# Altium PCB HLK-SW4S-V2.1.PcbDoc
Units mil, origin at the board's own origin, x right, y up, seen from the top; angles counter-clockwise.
Board outline 2716.54 x 2598.43 mil, 2 copper layers (Top Layer, Bottom Layer); 72 components, 59 nets, 226 pads, 137 vias.
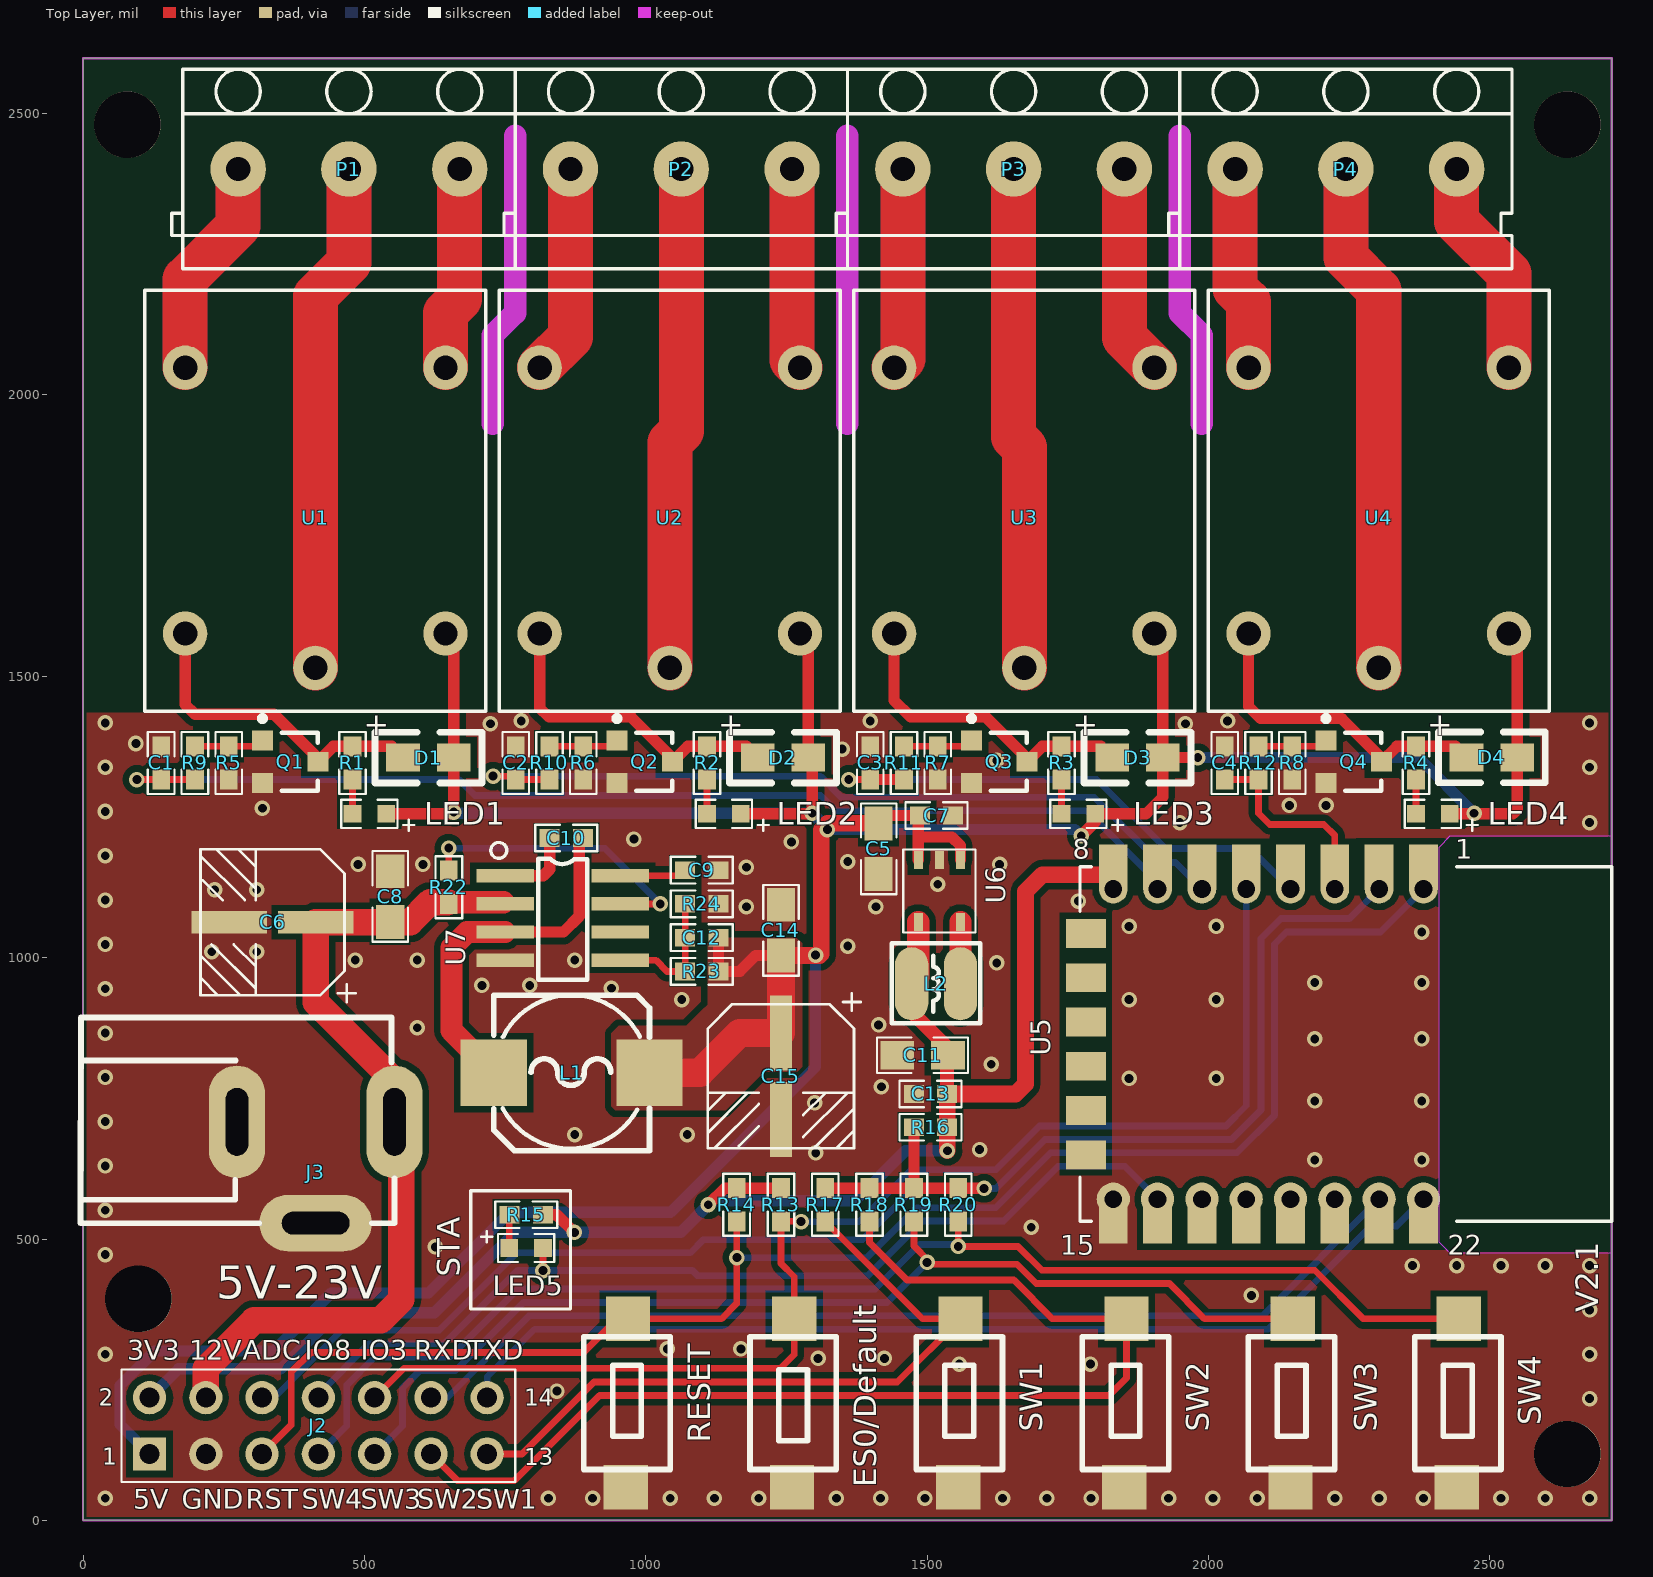
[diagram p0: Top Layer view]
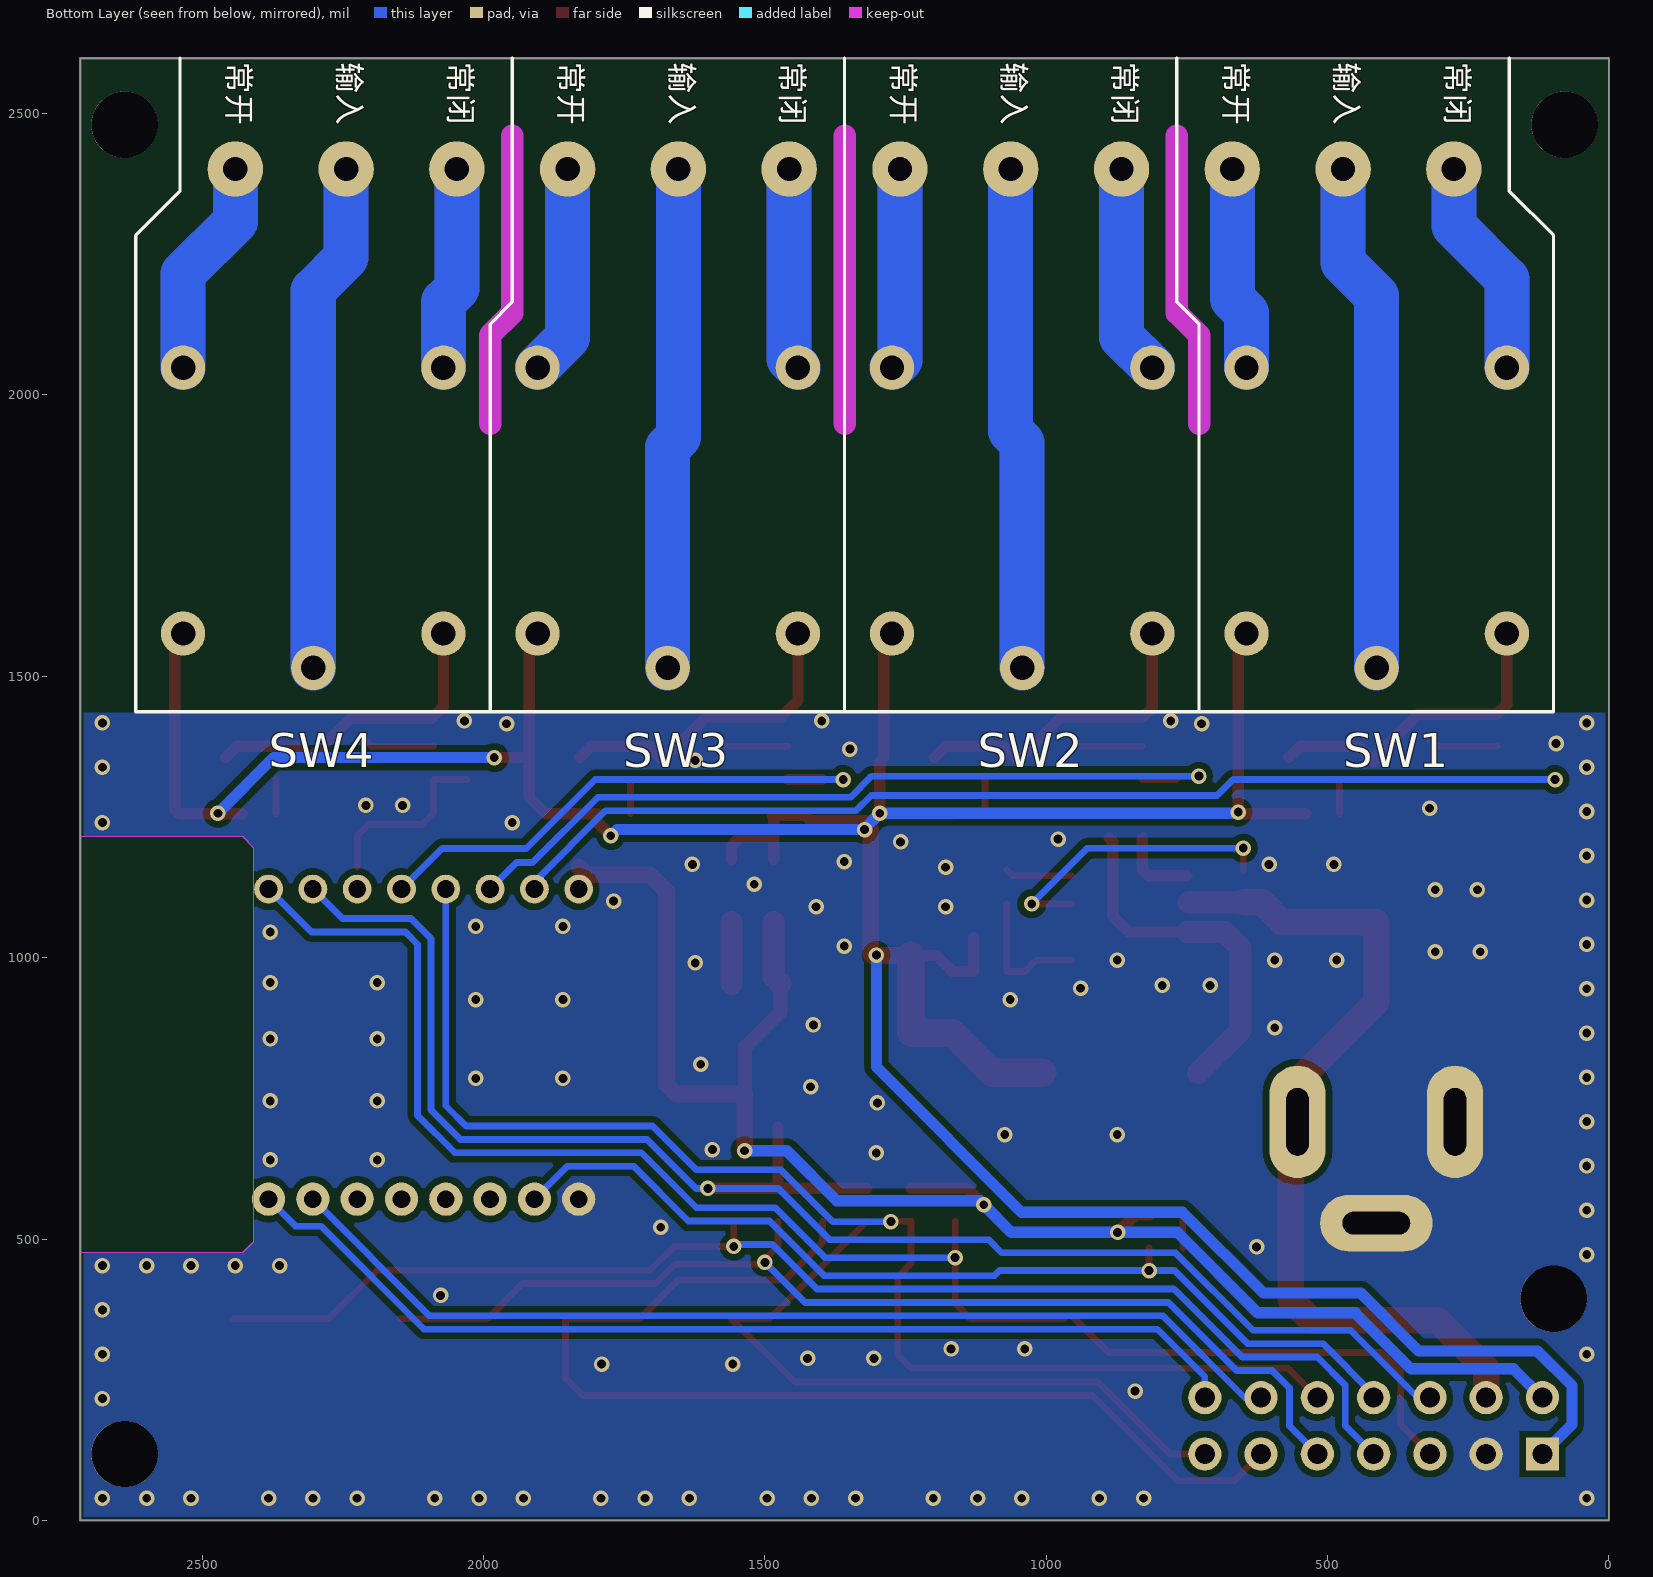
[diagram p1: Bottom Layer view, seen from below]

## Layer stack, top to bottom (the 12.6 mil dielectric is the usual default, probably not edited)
Top Layer: signal copper 1.4
Dielectric: dielectric 12.6, FR-4, Dk 4.8
Bottom Layer: signal copper 1.4

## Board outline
0,0 2716.54,0 2716.54,2598.43 0,2598.43

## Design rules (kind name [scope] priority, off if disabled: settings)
Clearance Clearance_1 [OnLayer('Keep-Out Layer')] p1: gap=3.94
Clearance [All] p2: gap=11.81
FabricationTestPointUsage TestPointUsage [All] p1: valid=0 allowmultiple=FALSE
FabricationTestpoint Testpoint [All] p1: side=3 testpointundercomponent=TRUE minsize=40 maxsize=100 preferedsize=60 minholesize=0 maxholesize=40 preferedholesize=32 testpointgrid=1 allowsidetop=TRUE allowsidebottom=TRUE usegrid=TRUE gridtolerance=0.01
PlaneConnect [All] p1: planeconnectstyle=Direct reliefexpansion=20 reliefentries=4 reliefconductorwidth=10 reliefairgap=10
PolygonConnect [All] p1: connectstyle=Direct reliefconductorwidth=10 reliefentries=4 polygonreliefangle="90 Angle" airgapwidth=10
RoutingVias [All] p1: holewidth=15.75 width=27.56 viastyle="Through Hole" minholewidth=15.75 minwidth=27.56 maxholewidth=15.75 maxwidth=27.56
SilkToSolderMaskClearance SilkscreenOverComponentPads [IsPad] p1: minsilkscreentomaskgap=10 clearancetoexposedcopper=TRUE
SolderMaskExpansion [All] p1: expansion=4
Width [All] p1: maxlimit=236.22 minlimit=10 preferedwidth=10
24 further rules are at their usual default settings.

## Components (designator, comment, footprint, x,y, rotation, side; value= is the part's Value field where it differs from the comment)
C1 "0.1uF" 0603L 138.74,1346.14 r270 top
C2 "0.1uF" 0603L 768.74,1346.14 r270 top
C3 "0.1uF" 0603L 1398.74,1346.14 r270 top
C4 "0.1uF" 0603L 2028.74,1346.14 r270 top
C5 "10uF/16V" 0805S 1413.74,1238.67 r270 top
C6 "220uF/35V" CAP_SMT_6.3 425.2,1062.99 r270 top
C7 "0.1uF" 0603L 1516.74,1252.67 r180 top
C8 "22uF" 0805S 545.74,1063.67 r90 top
C9 "0.1UF" 0603L 1099.53,1155.67 r180 top
C10 "0.1uF" 0603L 858.74,1212.67 r180 top
C11 "10uF/16V" 0805S 1536.85,826.77 r180 top
C12 "100pf" 0603L 1099.53,1035.67 r180 top
C13 "0.1uF" 0603L 1505.91,757.87 r0 top
C14 "0.1UF" 0805S 1240.16,1093.94 r270 top
C15 "220uF" CAP_SMT_6.3 1240.16,877.95 r0 top
D1 "1N4148" LED1 568.94,1355.43 r0 top
D2 "1N4148" LED1 1198.94,1355.43 r0 top
D3 "1N4148" LED1 1828.94,1355.43 r0 top
D4 "1N4148" LED1 2458.74,1355.67 r0 top
ES0/Default "SW-PB" KEY 1185.04,326.77 r270 top
J2 "HEADER 7X2" HDR2X7 118.11,118.11 r0 top
J3 "PWR2.5" POWER_STK1 413.39,728.35 r0 top
L1 "10uH" L7x7 730,795.67 r0 top
L2 "2.7uH" L322520 1559.06,953.78 r180 top
LED1 "LED" 0603LED 508.74,1255.67 r180 top
LED2 "LED" 0603LED 1138.74,1255.67 r180 top
LED3 "LED" 0603LED 1768.74,1255.67 r180 top
LED4 "LED" 0603LED 2398.74,1255.67 r180 top
LED5 "LED" 0603LED 787.4,484.25 r0 top
P1 "Header 3" 5MMX3 669.29,2401.57 r180 top
P2 "Header 3" 5MMX3 1259.84,2401.57 r180 top
P3 "Header 3" 5MMX3 1850.4,2401.57 r180 top
P4 "Header 3" 5MMX3 2440.95,2401.57 r180 top
Q1 "SS8050" SOT-23 367.95,1348.27 r270 top
Q2 "SS8050" SOT-23 997.95,1348.27 r270 top
Q3 "SS8050" SOT-23 1627.95,1348.27 r270 top
Q4 "SS8050" SOT-23 2257.95,1348.27 r270 top
R1 "1K" 0603L 478.74,1346.14 r270 top
R2 "1K" 0603L 1108.74,1346.14 r270 top
R3 "1K" 0603L 1738.74,1346.14 r270 top
R4 "1K" 0603L 2368.74,1346.14 r270 top
R5 "4.7K" 0603L 258.74,1346.14 r90 top
R6 "4.7K" 0603L 888.74,1346.14 r90 top
R7 "4.7K" 0603L 1518.74,1346.14 r90 top
R8 "4.7K" 0603L 2148.74,1346.14 r90 top
R9 "1K" 0603L 198.74,1346.14 r270 top
R10 "1K" 0603L 828.74,1346.14 r90 top
R11 "1K" 0603L 1458.74,1346.14 r270 top
R12 "1K" 0603L 2088.74,1346.14 r270 top
R13 "NC" 0603L 1240.16,561.02 r270 top
R14 "1K" 0603L 1161.42,561.02 r270 top
R15 "1K" 0603L 787.4,543.31 r0 top
R16 "10K" 0603L 1505.91,698.82 r0 top
R17 "521" 0603L 1318.9,561.02 r90 top
R18 "1.19K" 0603L 1397.64,561.02 r90 top
R19 "0" 0603L 1476.38,561.02 r90 top
R20 "3.04K" 0603L 1555.12,561.02 r90 top
R22 "10K" 0603L 650,1125.2 r90 top
R23 "47k" 0603L 1099.53,975.67 r0 top
R24 "10K" 0603L 1099.53,1095.67 r0 top
RESET "SW-PB" KEY 1043.31,90.55 r90 top
SW1 "SW-PB" KEY 1633.86,90.55 r90 top
SW2 "SW-PB" KEY 1929.13,90.55 r90 top
SW3 "SW-PB" KEY 2224.41,90.55 r90 top
SW4 "SW-PB" KEY 2519.68,90.55 r90 top
U1 "SRD-05VDC-SL-C" SRD-05VDC-SL-C 715.83,1438.27 r90 top
U2 "SRD-05VDC-SL-C" SRD-05VDC-SL-C 1345.75,1438.27 r90 top
U3 "SRD-05VDC-SL-C" SRD-05VDC-SL-C 1975.67,1438.27 r90 top
U4 "SRD-05VDC-SL-C" SRD-05VDC-SL-C 2605.59,1438.27 r90 top
U5 "WIFI MODULE" MOD1 1771.65,1161.42 r270 top
U6 "RT8009" SOT-25 1559.06,1173.78 r270 top
U7 "FR9886" SOP8 750.36,1140.67 r0 top

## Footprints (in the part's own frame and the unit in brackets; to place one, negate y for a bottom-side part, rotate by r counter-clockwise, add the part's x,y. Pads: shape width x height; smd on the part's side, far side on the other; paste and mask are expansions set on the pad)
5MMX3 [mm]
  round 2.5 hole 1.1: 1(0,0) 2(5,0) 3(10,0)
  silkscreen extent -2.5,-4.5 13,4.5
0603L [mm]
  rect 0.9x0.8 smd: 1(-0.75,0) 2(0.75,0)
  silkscreen extent -1.4,-0.6 1.4,0.6
0603LED [mm]
  rect 0.8x0.8 smd: 1(-0.762,0) 2(0.762,0)
  silkscreen extent -2.03,-0.64 1.27,0.76
0805S [mil]
  rect 60x50 smd: 1(0,0) 2(90,0)
  silkscreen extent -35,-31 126,31
CAP_SMT_6.3 [mm]
  rect 1x3.4 smd: 1(0,-0.3) 2(0,-4.2)
  silkscreen extent -3.3,-5.5 3.6,1.5
HDR2X7 [mm] "Connector; Header; 7x2 Position"
  rect 1.5x1.5 hole 0.9: 1(0,0)
  round 1.5 hole 0.9: 2(0,2.54) 3(2.54,0) 4(2.54,2.54) 5(5.08,0) 6(5.08,2.54) 7(7.62,0) 8(7.62,2.54) 9(10.16,0) 10(10.16,2.54) 11(12.7,0) 12(12.7,2.54) 13(15.24,0) 14(15.24,2.54)
  silkscreen extent -1.27,-1.27 16.51,3.81
KEY [mm]
  rect 2x2 smd: 1(-0.8,2) 2(6.8,1.9)
  silkscreen extent 0,0 6,3.9
L7x7 [mm]
  rect 3x3 smd: 1(0,0) 2(7.025,0)
  silkscreen extent 0,-3.53 7.03,3.5
L322520 [mm]
  oval 1.5x3.3 smd: 1(0,0) 2(2.2,0)
  silkscreen extent -0.9,-1.83 3.09,1.79
LED1 [mil]
  rect 60x50 smd: 1(-0.2,0.24) 2(89.8,0.24)
  silkscreen extent -50,-45 140,45
MOD1 [mm]
  rect 2x1.3 smd: 1(0,15.5) 2(0,13.5) 3(0,11.5) 4(0,9.5) 5(0,7.5) 6(0,5.5) 7(0,3.5) 8(0,1.5) 15(16,1.5) 16(16,3.5) 17(16,5.5) 18(16,7.5) 19(16,9.5) 20(16,11.5) 21(16,13.5) 22(16,15.5)
  round 1.3 hole 0.8: 1(1,15.5) 2(1,13.5) 3(1,11.5) 4(1,9.5) 5(1,7.5) 6(1,5.5) 7(1,3.5) 8(1,1.5)
  rect 1.3x1.8 smd: 9(3,0.262) 10(5,0.262) 11(7,0.262) 12(9,0.262) 13(11,0.262) 14(13,0.262)
  round 1.5 hole 0.8: 15(15,1.5) 16(15,3.5) 17(15,5.5) 18(15,7.5) 19(15,9.5) 20(15,11.5) 21(15,13.5) 22(15,15.5)
  silkscreen extent 0,0 16,24
POWER_STK1 [mil]
  oval 100x200 hole 40 slot 120 at 90 deg: 1(-140,-20) 2(140,-20)
  oval 200x100 hole 40 slot 120 at 0 deg: 3(0,-200)
  silkscreen extent -418,-200 140,165
SOP8 [mm] "Small Outline; 8 Leads; Body Width 4.3 mm; Pitch 1.27 mm"
  rect 2.6x0.6 smd: 1(-0.009,0.127) 2(-0.009,-1.143) 3(-0.009,-2.413) 4(-0.009,-3.683) 5(5.191,-3.683) 6(5.191,-2.413) 7(5.191,-1.143) 8(5.191,0.127)
  silkscreen extent 1.49,-4.57 3.69,0.89
SOT-23 [mm]
  rect 0.9x0.95 smd: 1(-0.95,-1.25) 2(0.95,-1.25) 3(0,1.25)
  silkscreen extent -2.07,-1.37 1.3,1.25
SOT-25 [mm]
  rect 0.8x0.4 smd: 1(0,0) 2(0,-0.95) 3(0,-1.9) 4(2.8,-1.9) 5(2.8,0)
  silkscreen extent -0.48,-2.58 3.28,0.68
SRD-05VDC-SL-C [mm]
  round 2 hole 1.1: 1(15.5,1.825) 2(15.5,13.575) 3(3.5,13.575) 4(1.95,7.7) 5(3.5,1.825)
  silkscreen extent 0,0 19,15.4

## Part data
C1 C2 C3 C4 C7 C8 C9 C10 C12 C13: library part Cap, "Capacitor"
C5 C6 C11 C15: library part "Cap Pol3", "Polarized Capacitor (Surface Mount)"
C14 R1 R2 R3 R4 R5 R6 R7 R8 R9 R10 R11 R12 R13 R14 R15 R16 R17 R18 R19 R20: library part Res2, "Resistor"
D1 D2 D3 D4: library part Diode, "Default Diode"
ES0/Default RESET SW1 SW2 SW3 SW4: "Switch"
J3: "Low Voltage Power Supply Connector"
L1 L2: library part INDUCTOR1
LED1 LED2 LED3 LED4 LED5: library part LED0, "Typical INFRARED GaAs LED"
P1 P2 P3 P4: "Header, 3-Pin"
Q1 Q2 Q3 Q4: library part 2N3904, "PNP General Purpose Amplifier"
R22 R23 R24: library part "0603_10 K_1%_1/10W", "RES, SO, 0603, 10K, 1%, 1/10W"
U1 U2 U3 U4: library part SRD
U5: library part MOD1

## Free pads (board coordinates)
  round 118.11 hole 118.11: 0(98.43,393.7) 0(2637.8,118.11) 0(2637.8,2480.32) 1(78.74,2480.32)

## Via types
v1: diameter 27.56, hole 15.75, Top Layer to Bottom Layer, tented both sides, 137 vias

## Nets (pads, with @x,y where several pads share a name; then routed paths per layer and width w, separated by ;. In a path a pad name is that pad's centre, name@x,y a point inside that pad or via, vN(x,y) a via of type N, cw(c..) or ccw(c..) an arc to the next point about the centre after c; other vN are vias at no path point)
5V: C5.1 C7.2 C12.1 C14.2 C15.1 D1.2 D2.2 D3.2 D4.2 J2.1 L1.2 LED1.1 LED2.1 LED3.1 LED4.1 R23.2 U1.5 U2.5 U3.5 U4.5 U6.1 U6.3 | length 6580.8
  Top Layer w19.68: U1.5 658.74,1561.3 D1.2
  Top Layer w20: LED1.1 655.74,1255.67 v1(658.74,1258.67) D1.2 ; C12.1 R23.2 1166.74,975.67 1195.01,1003.94 C14.2 ; LED2.1 1294.74,1255.67 v1(1295.74,1256.67) 1295.74,1348.67 D2.2 1288.74,1561.22 U2.5 ; C5.1 1427.74,1252.67 C7.2 ; U6.3 C7.2@1484.25,1241.18 ; 1486.74,1214.67 1543.74,1214.67 1559.06,1199.35 U6.1 ; v1(1773.74,1216.67) 1798.74,1241.67 LED3.1 1888.74,1255.67 1918.74,1285.67 D3.2 ; U3.5 1918.74,1561.14 D3.2 ; v1(1980.74,1355.67) D3.2 ; LED4.1 2540.74,1255.67 2548.54,1263.47 D4.2 2548.54,1561.27 U4.5
  Top Layer w29.53: C14.2 1309.01,1003.94 1311.74,1006.67 v1@1311.74,1227.67 ; v1@1322.74,1238.67 C5.1
  Top Layer w50: L1.2 1096,795.67 1166.47,866.14 C15.1 C14.2
  Bottom Layer w20: J2.1 65.74,170.48 65.74,239.67 127.33,301.26 338.26,301.26 441,404 614,404 757.59,547.59 1043.59,547.59 1301.74,805.74 v1(1301.74,1004.67) ; v1(658.74,1258.67) 660.74,1256.67 v1(1295.74,1256.67) v1@1324.74,1227.67 ; v1(1322.74,1227.67) v1@1324.74,1227.67 ; v1(1773.74,1216.67) 1762.74,1227.67 v1@1324.74,1227.67 ; v1(1980.74,1355.67) 2372.74,1355.67 v1(2471.74,1256.67)
ADC: J2.6 R16.1 R17.2 R18.2 R19.2 R20.2 U5.2 | length 2928.3
  Top Layer w20: R17.2 R18.2 R19.2 ; R16.1 R19.2 ; v1(1601,590) 1600.45,590.55 R20.2 R19.2
  Bottom Layer w12: J2.6 339.43,218.11 459.32,338 632.32,338 769.91,475.59 1079,475.59 1102.41,499 1385,499 1476,590 v1(1601,590) 1622.33,590 1709.52,677.19 2040.86,677.19 2093.19,729.52 2093.19,1033.86 2128.81,1069.48 2250.58,1069.48 U5.2@2303.15,1122.05
GND: C1.1 C2.1 C3.1 C4.1 C5.2 C6.2 C7.1 C8.2 C9.1 C11.2 C13.1 C14.1 C15.2 ES0/Default.2 J2.3 J3.1 J3.3 pad.0@98.43,393.7 pad.0@2637.8,118.11 Q1.2 Q2.2 Q3.2 Q4.2 R5.1 R6.1 R7.1 R8.1 R24.2 RESET.1 SW1.1 SW2.1 SW3.1 SW4.1 U5.15 U6.2 U7.4
  other v1: 39.37,39.37 826.77,39.37 905.51,39.37 1043.31,39.37 1122.05,39.37 1200.79,39.37 1338.58,39.37 1417.32,39.37 1496.06,39.37 1633.86,39.37 1712.6,39.37 1791.34,39.37 1929.13,39.37 2007.87,39.37 2086.61,39.37 2224.41,39.37 2303.15,39.37 2381.89,39.37 2519.69,39.37 2598.43,39.37 2677.17,39.37 2677.17,216.54 842,230 1557,278 1790,278 1306,288 1424,288 39.37,295.28 2677.17,295.28 1038,305 1169,305 2677.17,374.02 2076,400 2362.2,452.76 2440.94,452.76 2519.69,452.76 2598.43,452.76 2677.17,452.76 39.37,472.44 626,486 1685,521 39.37,551.18 39.37,629.92 2188.74,640.67 2378.74,640.67 1302,653 1593,659 873.74,685.67 1073.74,685.67 39.37,708.66 1300,742 2188.74,745.67 2378.74,745.67 1418.74,770.67 1858.74,785.67 2013.74,785.67 39.37,787.4 1613.74,810.67 2188.74,855.67 2378.74,855.67 39.37,866.14 593.74,875.67 1413.74,880.67 1063.74,925.67 1858.74,925.67 2013.74,925.67 39.37,944.88 938.74,945.67 708.74,950.67 793.74,950.67 2188.74,955.67 2378.74,955.67 1623.74,990.67 483.74,995.67 593.74,995.67 873.74,995.67 228.74,1010.67 308.74,1010.67 1358.74,1020.67 39.37,1023.62 2378.74,1045.67 1858.74,1055.67 2013.74,1055.67 1178.74,1090.67 1408.74,1090.67 1768.74,1100.67 39.37,1102.36 233.74,1120.67 308.74,1120.67 1518.74,1130.67 1178.74,1160.67 488.74,1165.67 603.74,1165.67 1628.74,1165.67 1358.74,1170.67 39.37,1181.1 1258.74,1205.67 978.74,1210.67 1948.82,1240.16 2677.17,1240.16 39.37,1259.84 318.74,1265.67 2143.74,1270.67 2208.74,1270.67 39.37,1338.58 2677.17,1338.58 1623.74,1350.67 1348.74,1370.67 93.74,1380.67 723.74,1415.67 1958.74,1415.67 39.37,1417.32 2677.17,1417.32 778.74,1420.67 1398.74,1420.67 2033.74,1420.67
IO0: U5.12
IO1: C4.2 R12.2 U5.3 | length 327.6
  Top Layer w12: C4.2 R12.2 2088.74,1256.67 2108.74,1236.67 2204.74,1236.67 2224.41,1217 U5.3@2224.41,1161.42
IO2: C3.2 R11.2 U5.4 | length 963.6
  Top Layer w12: v1(1360.74,1316.67) 1398.69,1316.67 C3.2
  Top Layer w19.68: C3.2 R11.2
  Bottom Layer w12: v1(1360.74,1316.67) 1801.33,1316.67 1924,1194 2073.72,1194 U5.4@2145.67,1122.05
IO3: ES0/Default.1 J2.10 R13.2 U5.5 | length 2321.4
  Top Layer w12: J2.10 570.67,270.67 1239.74,270.67 1263.78,294.71 ES0/Default.1 1263.78,433.07 1240.16,456.69 R13.2 1275.5,531.5 v1(1276,531)
  Bottom Layer w12: v1(1276,531) 1379.43,531 1471.43,623 1621.65,623 1699.65,701 2031,701 2066.93,736.93 U5.5@2066.93,1122.05
IO4: U5.13
IO5: U5.14
IO7: U5.17
IO8: J2.8 LED5.2 U5.16 | length 1737.5
  Top Layer w12: v1(817,444) 817.4,444.4 LED5.2
  Bottom Layer w12: J2.8 418.11,224.11 508.19,314.19 642.18,314.19 771.99,444 v1(817,444) 1083,444 1092,435 1394.67,435 1491.67,532 1636,532 1733.57,629.57 1850.75,629.57 U5.16@1909.45,570.87
IO9: U5.18
IO12: C1.2 R9.2 U5.7 | length 2004.7
  Top Layer w12: v1(95.74,1316.67) 95.8,1316.61 C1.2 R9.2
  Bottom Layer w12: v1(95.74,1316.67) 667.74,1316.67 696.15,1288.26 1310.8,1288.26 1337.79,1261.27 1782.74,1261.27 1909.45,1134.56 U5.7@1909.45,1122.05
IO13: C2.2 R10.1 U5.6 | length 1445.1
  Top Layer w12: v1(728.74,1322.67) 762.69,1322.67 C2.2 R10.1
  Bottom Layer w12: v1(728.74,1322.67) 1310.06,1322.67 1347.65,1285.08 1796.92,1285.08 1912.76,1169.24 1941,1169.24 U5.6@1988.19,1122.05
IO21: U5.11
IO22: U5.10
IO23: U5.9
NetC9_2: C9.2 U7.8 | length 119.4
  Top Layer w12: U7.8 1060,1145.67 C9.2
NetC10_1: C10.1 L1.1 U7.3 | length 645.1
  Top Layer w20: U7.3 853.74,1045.67 881.73,1073.66 881.73,1206.13 C10.1
  Top Layer w39.37: L1.1 654.74,870.93 654.74,1017.67 682.74,1045.67 U7.3
NetC10_2: C10.2 U7.1 | length 139.5
  Top Layer w20: U7.1 817.74,1145.67 829.21,1157.14 C10.2
NetC12_2: C12.2 R23.1 R24.1 U7.5 | length 243.6
  Top Layer w12: U7.5 1017.74,995.67 1037.74,975.67 R23.1 C12.2 R24.1
NetD1_1: D1.1 Q1.3 R1.1 U1.3 | length 578.8
  Top Layer w20: U1.3 181.38,1450.03 198.74,1432.67 339,1432.67 417.16,1354.51 Q1.3 444.56,1375.67 R1.1 548.74,1375.67 D1.1
NetD2_1: D2.1 Q2.3 R2.1 U2.3 | length 582.4
  Top Layer w20: U2.3 811.3,1444.11 827.74,1427.67 974,1427.67 1047.16,1354.51 Q2.3 1074.56,1375.67 R2.1 1178.74,1375.67 D2.1
NetD3_1: D3.1 Q3.3 R3.1 U3.3 | length 574.8
  Top Layer w20: U3.3 1441.22,1457.19 1470.74,1427.67 1604,1427.67 1677.16,1354.51 Q3.3 1704.56,1375.67 R3.1 1808.74,1375.67 D3.1
NetD4_1: D4.1 Q4.3 R4.1 U4.3 | length 581
  Top Layer w20: U4.3 2071.14,1446.27 2092.21,1425.2 2236.48,1425.2 2307.16,1354.51 Q4.3 2334.56,1375.67 R4.1 2438.77,1375.67 D4.1
NetL2_1: L2.1 U6.5 | length 109.8
  Top Layer w39.37: L2.1 U6.5
NetLED1_2: LED1.2 R1.2 | length 60.9
  Top Layer w12: LED1.2 R1.2
NetLED2_2: LED2.2 R2.2 | length 60.9
  Top Layer w12: LED2.2 R2.2
NetLED3_2: LED3.2 R3.2 | length 60.9
  Top Layer w12: LED3.2 R3.2
NetLED4_2: LED4.2 R4.2 | length 60.9
  Top Layer w12: LED4.2 R4.2
NetLED5_1: LED5.1 R15.1 | length 59.3
  Top Layer w12: LED5.1 757.4,542.83 R15.1
NetP1_1: P1.1 U1.1 | length 727.1
  Top Layer w80: U1.1 643.98,2145.67 669.29,2170.99 P1.1
  Bottom Layer w80: U1.1 643.98,2145.67 669.29,2170.99 P1.1
NetP1_2: P1.2 U1.4 | length 1822.6
  Top Layer w80: U1.4 412.68,2175.67 472.44,2235.43 P1.2
  Bottom Layer w80: U1.4 412.68,2175.67 472.44,2235.43 P1.2
NetP1_3: P1.3 U1.2 | length 784.2
  Top Layer w80: U1.2 181.38,2205.67 275.59,2299.88 P1.3
  Bottom Layer w80: U1.2 181.38,2205.67 275.59,2299.88 P1.3
NetP2_1: P2.1 U2.1 | length 717.8
  Top Layer w80: P2.1 1259.84,2062.56 U2.1
  Bottom Layer w80: P2.1 1259.84,2062.56 U2.1
NetP2_2: P2.2 U2.4 | length 1790
  Top Layer w80: U2.4 1042.6,1915.27 1062.99,1935.67 P2.2
  Bottom Layer w80: U2.4 1042.6,1915.27 1062.99,1935.67 P2.2
NetP2_3: P2.3 U2.2 | length 751.6
  Top Layer w80: U2.2 866.14,2103.35 P2.3
  Bottom Layer w80: U2.2 866.14,2103.35 P2.3
NetP3_1: P3.1 U3.1 | length 750.4
  Top Layer w80: P3.1 1850.4,2101.93 U3.1
  Bottom Layer w80: P3.1 1850.4,2101.93 U3.1
NetP3_2: P3.2 U3.4 | length 1788.8
  Top Layer w80: P3.2 1653.55,1925.67 1672.52,1906.69 U3.4
  Bottom Layer w80: P3.2 1653.55,1925.67 1672.52,1906.69 U3.4
NetP3_3: P3.3 U3.2 | length 719
  Top Layer w80: U3.2 1456.69,2063.98 P3.3
  Bottom Layer w80: U3.2 1456.69,2063.98 P3.3
NetP4_1: P4.1 U4.1 | length 783
  Top Layer w80: P4.1 2440.95,2308.46 2533.74,2215.67 U4.1
  Bottom Layer w80: P4.1 2440.95,2308.46 2533.74,2215.67 U4.1
NetP4_2: P4.2 U4.4 | length 1821.4
  Top Layer w80: P4.2 2244.1,2244.01 2302.44,2185.67 U4.4
  Bottom Layer w80: P4.2 2244.1,2244.01 2302.44,2185.67 U4.4
NetP4_3: P4.3 U4.2 | length 725.9
  Top Layer w80: P4.3 2047.24,2189.57 2071.14,2165.67 U4.2
  Bottom Layer w80: P4.3 2047.24,2189.57 2071.14,2165.67 U4.2
NetQ1_1: Q1.1 R5.2 R9.1 | length 124.1
  Top Layer w12: R9.1 R5.2 308.74,1375.67 Q1.1
NetQ2_1: Q2.1 R6.2 R10.2 | length 124.1
  Top Layer w12: R10.2 R6.2 938.74,1375.67 Q2.1
NetQ3_1: Q3.1 R7.2 R11.1 | length 124.1
  Top Layer w12: R11.1 R7.2 1568.74,1375.67 Q3.1
NetQ4_1: Q4.1 R8.2 R12.1 | length 124.1
  Top Layer w12: R12.1 R8.2 2198.74,1375.67 Q4.1
NetR22_2: R22.2 U7.7 | length 528.1
  Top Layer w12: v1(649.74,1194.67) 649.74,1154.99 R22.2 ; U7.7 v1(1025.74,1095.67)
  Bottom Layer w12: v1(649.74,1194.67) 926.74,1194.67 v1(1025.74,1095.67)
REST: J2.5 R14.2 RESET.2 U5.1 | length 2804.9
  Top Layer w12: J2.5 369.74,169.74 369.74,263.67 404.74,298.67 889.22,298.67 RESET.2@948.82,358.27 ; RESET.2 1134.27,358.27 1161.42,385.42 R14.2
  Bottom Layer w12: v1(1162,467) 1393,467 1481.81,555.81 1621.81,555.81 1719.38,653.38 2050.73,653.38 2117,719.65 2117,1024 2138.67,1045.67 2305.51,1045.67 U5.1@2381.89,1122.05
RXD: J2.12 U5.21 | length 1831.2
  Bottom Layer w12: J2.12 647.12,218.11 792.58,363.57 2095.85,363.57 U5.21@2303.15,570.87
SW1: J2.13 R17.1 SW1.2 | length 1252.3
  Top Layer w12: J2.13 780.11,118.11 908.07,246.07 1446.86,246.07 SW1.2 1492.13,358.27 R17.1
SW2: J2.11 R18.1 SW2.2 | length 1987.1
  Top Layer w12: J2.11 665.55,70.67 766.34,70.67 917.93,222.26 1823.33,222.26 1854.33,253.26 SW2.2 1722.73,358.27 1653.92,427.08 1464.33,427.08 1397.64,493.77 R18.1
SW3: J2.9 R19.1 SW3.2 | length 1934.8
  Top Layer w12: R19.1 1476.38,487.67 v1@1502.56,461.49 ; v1(1499.74,458.67) 1502.95,455.46 1659.22,455.46 1693.82,420.86 1930.55,420.86 1993.14,358.27 SW3.2
  Bottom Layer w12: J2.9 567.74,167.74 567.74,235.74 598.57,266.57 661.91,266.57 782.72,387.38 1428.45,387.38 v1(1499.74,458.67)
SW4: J2.7 R20.1 SW4.2 | length 2322.2
  Top Layer w12: R20.1 v1(1555.12,487.05) 1661.3,487.05 1703.68,444.67 2188.74,444.67 2275.14,358.27 SW4.2
  Bottom Layer w12: J2.7 468.74,168.74 468.74,240.74 518.38,290.38 652.04,290.38 772.85,411.19 1407.58,411.19 1486.65,490.26 1551.91,490.26 v1(1555.12,487.05)
TXD: J2.14 U5.22 | length 1831.8
  Bottom Layer w12: J2.14 718.11,255.42 802.44,339.76 2105.76,339.76 2288.99,522.99 2334.01,522.99 U5.22@2381.89,570.87
USBDN: U5.19
USBDP: U5.20
V3.3: C11.1 C13.2 J2.2 L2.2 R13.1 R14.1 R15.2 R16.2 U5.8 U6.4 | length 2900.7
  Top Layer w20: R15.2 841.69,543.31 v1(873,512) ; v1(1111,561) 1140.55,590.55 R14.1 R13.1
  Top Layer w25: L2.2 1472.44,903.97 1535.43,840.98 C13.2
  Top Layer w29.53: v1(1536,657) 1535.43,657.57 C13.2 1656.94,757.87 1674.74,775.67 1674.74,1117.67 1704.74,1147.67 1816.96,1147.67 U5.8@1830.71,1161.42
  Top Layer w39.37: L2.2 1484.25,965.59 U6.4
  Bottom Layer w20: J2.2 169.45,269.45 351.44,269.45 450.99,369 623.99,369 766.99,512 v1(873,512) 1062,512 v1(1111,561) ; v1@1118,568 1372,568 1461,657 v1(1536,657)
VCC12V: C6.1 C8.1 J2.4 J3.2 R22.1 U7.2 | length 1530.4
  Top Layer w39.37: R22.1 653,1098.67 U7.2@747,1098.67
  Top Layer w47.24: J2.4 218.11,270.04 303.74,355.67 528.74,355.67 565.74,392.67 565.74,695.99 J3.2 553.39,781.02 413.39,921.02 C6.1 581.06,1062.99 616.74,1098.67 R22.1@647,1098.67
pads on no net: U7.6

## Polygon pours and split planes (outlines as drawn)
GND on Top Layer "Top Layer-No Net" (solid, remove dead copper, pour order 6): 0,0 2716.54,0 2716.54,1435.67 0,1435.67
5V on Top Layer "Top Layer-No Net" (solid, remove dead copper, pour order 4): 960.74,728.67 1141.74,728.67 1200.74,787.67 1210.74,797.67 1235.74,797.67 1268.74,797.67 1277.74,806.67 1277.74,1025.67 1267.74,1035.67 1119.74,1035.67 1109.74,1025.67 1109.74,916.67 1099.74,906.67 1071.74,878.67 995.74,878.67 951.74,878.67 938.74,865.67 938.74,735.67 942.74,731.67 945.74,728.67 959.74,728.67
GND on Bottom Layer "Top Layer-No Net" (solid, remove dead copper, pour order 5): 0,0 2716.54,0 2716.54,1435.67 0,1435.67

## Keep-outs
Keep-Out Layer:
  pour cut-out: 2716.54,1215.67 2428.74,1215.67 2408.74,1195.67 2408.74,495.67 2428.74,475.67 2716.54,475.67
  lines w3.94: 0,0 0,2598.43 2716.54,2598.43 2716.54,0 0,0
  lines w40: 728.35,1948.82 728.35,2106.3 767.72,2145.67 767.72,2460.63 ; 1358.27,1948.82 1358.27,2460.63 ; 1948.82,2460.63 1948.82,2145.67 1988.19,2106.3 1988.19,1948.82

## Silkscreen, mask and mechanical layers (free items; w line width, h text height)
Top Overlay:
  circle w5.91: c738.74,1190.67 r14.14
  lines w5.91: 688.98,375.67 688.98,585.67 866.14,585.67 866.14,375.67 688.98,375.67
  text "8" at 1758.74,1175.67 h35
  text "1" at 2438.74,1175.67 h35
  text "15" at 1736.22,472.44 h35
  text "22" at 2425.2,472.44 h35
  text "STA" at 669.29,433.07 h40 r90
  text "5V-23V" at 236.22,393.7 h59.06
  text "V2.1" at 2692.91,370.08 h40 r90
  text "3V3" at 78.74,285.67 h35
  text "12V" at 188.74,285.67 h35
  text "ADC" at 283.74,285.67 h35
  text "IO8" at 393.74,285.67 h35
  text "IO3" at 493.74,285.67 h35
  text "RXD" at 588.74,285.67 h35
  text "TXD" at 683.74,285.67 h35
  text "5V" at 88.74,20.67 h35
  text "GND" at 175.74,20.67 h35
  text "RST" at 288.74,20.67 h35
  text "SW4" at 388.74,20.67 h35
  text "SW3" at 493.74,20.67 h35
  text "SW2" at 593.74,20.67 h35
  text "SW1" at 698.74,20.67 h35
Bottom Overlay:
  lines w5.91: 177.17,2598.43 177.17,2362.2 98.43,2283.46 98.43,1437.01 2618.11,1437.01 2618.11,2283.46 2539.37,2362.2 2539.37,2598.43 ; 728.35,1437.01 728.35,2125.98 767.72,2165.35 767.72,2598.43 ; 1358.27,1437.01 1358.27,2598.43 ; 1948.82,2598.43 1948.82,2165.35 1988.19,2125.98 1988.19,1437.01
  text "常闭" at 301.82,2590.88 h70 r90
  text "输入" at 498.67,2590.88 h70 r90
  text "常开" at 695.52,2590.88 h70 r90
  text "常闭" at 892.37,2590.88 h70 r90
  text "输入" at 1089.22,2590.88 h70 r90
  text "常开" at 1286.07,2590.88 h70 r90
  text "常闭" at 1482.92,2590.88 h70 r90
  text "输入" at 1679.77,2590.88 h70 r90
  text "常开" at 1876.62,2590.88 h70 r90
  text "常闭" at 2073.47,2590.88 h70 r90
  text "输入" at 2270.32,2590.88 h70 r90
  text "常开" at 2467.17,2590.88 h70 r90
  text "SW1" at 472.44,1338.58 h60
  text "SW2" at 1122.05,1338.58 h60
  text "SW3" at 1751.97,1338.58 h60
  text "SW4" at 2381.89,1338.58 h60
Bottom Solder:
  lines w80: 181.38,2048.5 181.38,2205.67 275.59,2299.88 275.59,2401.57 ; 412.68,1515.04 412.68,2175.67 472.44,2235.43 472.44,2401.57 ; 643.98,2048.5 643.98,2145.67 669.29,2170.99 669.29,2401.57 ; 811.3,2048.5 866.14,2103.35 866.14,2401.57 ; 1042.6,1515.04 1042.6,1915.27 1062.99,1935.67 1062.99,2401.57 ; 1259.84,2401.57 1259.84,2062.56 1273.9,2048.5 ; 1441.22,2048.5 1456.69,2063.98 1456.69,2401.57 ; 1653.55,2401.57 1653.55,1925.67 1672.52,1906.69 1672.52,1515.04 ; 1850.4,2401.57 1850.4,2101.93 1903.82,2048.5 ; 2047.24,2401.57 2047.24,2189.57 2071.14,2165.67 2071.14,2048.5 ; 2244.1,2401.57 2244.1,2244.01 2302.44,2185.67 2302.44,1515.04 ; 2440.95,2401.57 2440.95,2308.46 2533.74,2215.67 2533.74,2048.5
